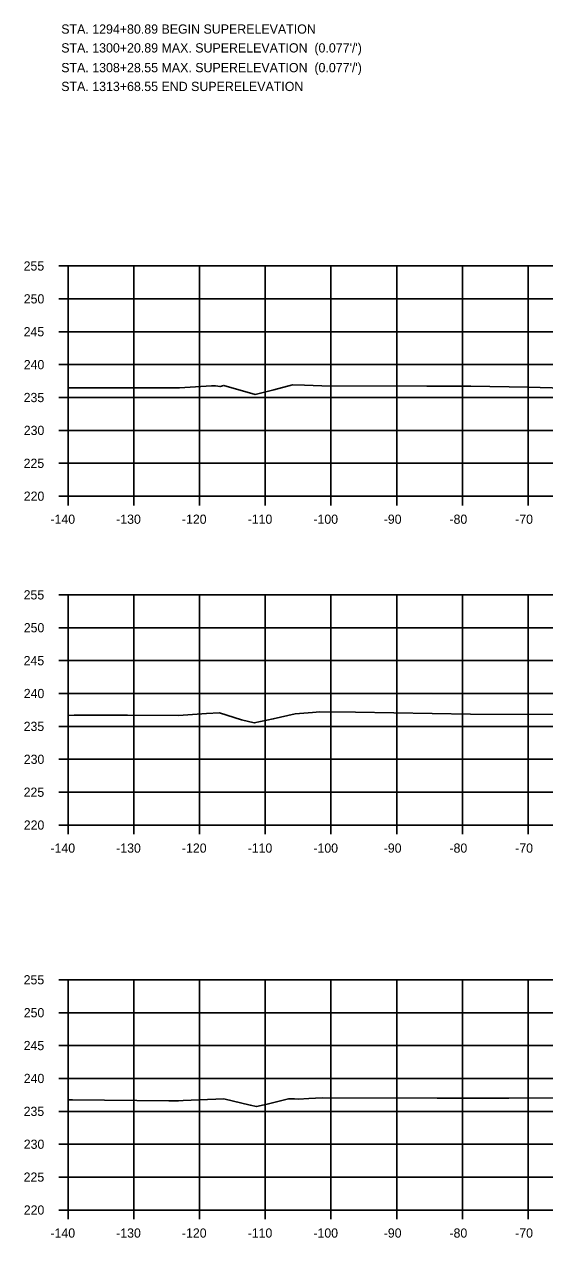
# Model space of a CAD drawing. Extents: x 1342547 to 1344156, y -1532351 to -1517216.
# Drawn here: x 1342556.2 to 1342635.4, y -1517828.4 to -1517643.9 of the extents above; entities that cross this region are included whole.
import ezdxf

# ---------------------------------------------------------------- set-up
doc = ezdxf.new("R2010")
doc.units = 0
for name, color, linetype in [('R_Axis', 7, 'Continuous'), ('R_Axis Annot', 7, 'Continuous'), ('R_Border Notes', 7, 'Continuous'), ('R_Exist Surface', 7, 'Continuous'), ('R_Grid', 7, 'Continuous')]:
    doc.layers.add(name, color=color, linetype=linetype)

msp = doc.modelspace()

# ---------------------------------------------------------------- linework, layer by layer
at = {"layer": 'R_Axis'}
for p, q in [((1342561.47, -1517680.65), (1342562.87, -1517680.65)), ((1342562.87, -1517715.65), (1342562.87, -1517680.65)), ((1342561.47, -1517685.65), (1342562.87, -1517685.65)), ((1342561.47, -1517690.65), (1342562.87, -1517690.65)), ((1342561.47, -1517695.65), (1342562.87, -1517695.65)), ((1342561.47, -1517700.65), (1342562.87, -1517700.65)), ((1342561.47, -1517705.65), (1342562.87, -1517705.65)), ((1342561.47, -1517710.65), (1342562.87, -1517710.65)), ((1342561.47, -1517715.65), (1342562.87, -1517715.65)), ((1342562.87, -1517715.65), (1342842.87, -1517715.65)), ((1342562.87, -1517717.05), (1342562.87, -1517715.65)), ((1342572.87, -1517717.05), (1342572.87, -1517715.65)), ((1342582.87, -1517717.05), (1342582.87, -1517715.65)), ((1342592.87, -1517717.05), (1342592.87, -1517715.65)), ((1342602.87, -1517717.05), (1342602.87, -1517715.65)), ((1342612.87, -1517717.05), (1342612.87, -1517715.65)), ((1342622.87, -1517717.05), (1342622.87, -1517715.65)), ((1342632.87, -1517717.05), (1342632.87, -1517715.65)), ((1342561.47, -1517730.65), (1342562.87, -1517730.65)), ((1342562.87, -1517765.65), (1342562.87, -1517730.65)), ((1342561.47, -1517735.65), (1342562.87, -1517735.65)), ((1342561.47, -1517740.65), (1342562.87, -1517740.65)), ((1342561.47, -1517745.65), (1342562.87, -1517745.65)), ((1342561.47, -1517750.65), (1342562.87, -1517750.65)), ((1342561.47, -1517755.65), (1342562.87, -1517755.65)), ((1342561.47, -1517760.65), (1342562.87, -1517760.65)), ((1342561.47, -1517765.65), (1342562.87, -1517765.65)), ((1342562.87, -1517765.65), (1342842.87, -1517765.65)), ((1342562.87, -1517767.05), (1342562.87, -1517765.65)), ((1342572.87, -1517767.05), (1342572.87, -1517765.65)), ((1342582.87, -1517767.05), (1342582.87, -1517765.65)), ((1342592.87, -1517767.05), (1342592.87, -1517765.65)), ((1342602.87, -1517767.05), (1342602.87, -1517765.65)), ((1342612.87, -1517767.05), (1342612.87, -1517765.65)), ((1342622.87, -1517767.05), (1342622.87, -1517765.65)), ((1342632.87, -1517767.05), (1342632.87, -1517765.65)), ((1342561.47, -1517789.17), (1342562.87, -1517789.17)), ((1342562.87, -1517824.17), (1342562.87, -1517789.17)), ((1342561.47, -1517794.17), (1342562.87, -1517794.17)), ((1342561.47, -1517799.17), (1342562.87, -1517799.17)), ((1342561.47, -1517804.17), (1342562.87, -1517804.17)), ((1342561.47, -1517809.17), (1342562.87, -1517809.17)), ((1342561.47, -1517814.17), (1342562.87, -1517814.17)), ((1342561.47, -1517819.17), (1342562.87, -1517819.17)), ((1342561.47, -1517824.17), (1342562.87, -1517824.17)), ((1342562.87, -1517824.17), (1342842.87, -1517824.17)), ((1342562.87, -1517825.57), (1342562.87, -1517824.17)), ((1342572.87, -1517825.57), (1342572.87, -1517824.17)), ((1342582.87, -1517825.57), (1342582.87, -1517824.17)), ((1342592.87, -1517825.57), (1342592.87, -1517824.17)), ((1342602.87, -1517825.57), (1342602.87, -1517824.17)), ((1342612.87, -1517825.57), (1342612.87, -1517824.17)), ((1342622.87, -1517825.57), (1342622.87, -1517824.17)), ((1342632.87, -1517825.57), (1342632.87, -1517824.17))]:
    msp.add_line(p, q, dxfattribs=at)
at = {"layer": 'R_Exist Surface'}
for points in [[(1342562.87, -1517699.19), (1342563.82, -1517699.18), (1342571.12, -1517699.16), (1342579.82, -1517699.2), (1342584.7, -1517698.89), (1342585.29, -1517698.85), (1342586.01, -1517698.99), (1342586.58, -1517698.81), (1342591.34, -1517700.17), (1342594.18, -1517699.46), (1342597.02, -1517698.71), (1342598.86, -1517698.75), (1342601.47, -1517698.89), (1342617.46, -1517698.9), (1342624.14, -1517698.95), (1342632.87, -1517699.07), (1342645.61, -1517699.41)], [(1342562.87, -1517748.97), (1342563.8, -1517748.95), (1342571.91, -1517748.96), (1342579.69, -1517748.99), (1342583.96, -1517748.69), (1342585.91, -1517748.58), (1342589.24, -1517749.63), (1342591.19, -1517750.13), (1342594.08, -1517749.51), (1342597.41, -1517748.76), (1342600.08, -1517748.54), (1342601.2, -1517748.46), (1342606.62, -1517748.48), (1342624.08, -1517748.77), (1342640.07, -1517748.84)], [(1342562.87, -1517807.41), (1342563.57, -1517807.41), (1342578.2, -1517807.56), (1342579.67, -1517807.56), (1342580.41, -1517807.52), (1342586.58, -1517807.29), (1342590.6, -1517808.22), (1342591.52, -1517808.45), (1342593.15, -1517808.07), (1342596.39, -1517807.27), (1342597.3, -1517807.29), (1342597.94, -1517807.3), (1342599.5, -1517807.23), (1342601.53, -1517807.11), (1342619.03, -1517807.17), (1342623.92, -1517807.17), (1342629.95, -1517807.17), (1342648.58, -1517807.13)]]:
    msp.add_lwpolyline(points, dxfattribs=at)
at = {"layer": 'R_Grid'}
for p, q in [((1342562.87, -1517680.65), (1342842.87, -1517680.65)), ((1342562.87, -1517715.65), (1342562.87, -1517680.65)), ((1342572.87, -1517715.65), (1342572.87, -1517680.65)), ((1342582.87, -1517715.65), (1342582.87, -1517680.65)), ((1342592.87, -1517715.65), (1342592.87, -1517680.65)), ((1342602.87, -1517715.65), (1342602.87, -1517680.65)), ((1342612.87, -1517715.65), (1342612.87, -1517680.65)), ((1342622.87, -1517715.65), (1342622.87, -1517680.65)), ((1342632.87, -1517715.65), (1342632.87, -1517680.65)), ((1342562.87, -1517685.65), (1342842.87, -1517685.65)), ((1342562.87, -1517690.65), (1342842.87, -1517690.65)), ((1342562.87, -1517695.65), (1342842.87, -1517695.65)), ((1342562.87, -1517700.65), (1342842.87, -1517700.65)), ((1342562.87, -1517705.65), (1342842.87, -1517705.65)), ((1342562.87, -1517710.65), (1342842.87, -1517710.65)), ((1342562.87, -1517715.65), (1342842.87, -1517715.65)), ((1342562.87, -1517730.65), (1342842.87, -1517730.65)), ((1342562.87, -1517765.65), (1342562.87, -1517730.65)), ((1342572.87, -1517765.65), (1342572.87, -1517730.65)), ((1342582.87, -1517765.65), (1342582.87, -1517730.65)), ((1342592.87, -1517765.65), (1342592.87, -1517730.65)), ((1342602.87, -1517765.65), (1342602.87, -1517730.65)), ((1342612.87, -1517765.65), (1342612.87, -1517730.65)), ((1342622.87, -1517765.65), (1342622.87, -1517730.65)), ((1342632.87, -1517765.65), (1342632.87, -1517730.65)), ((1342562.87, -1517735.65), (1342842.87, -1517735.65)), ((1342562.87, -1517740.65), (1342842.87, -1517740.65)), ((1342562.87, -1517745.65), (1342842.87, -1517745.65)), ((1342562.87, -1517750.65), (1342842.87, -1517750.65)), ((1342562.87, -1517755.65), (1342842.87, -1517755.65)), ((1342562.87, -1517760.65), (1342842.87, -1517760.65)), ((1342562.87, -1517765.65), (1342842.87, -1517765.65)), ((1342562.87, -1517789.17), (1342842.87, -1517789.17)), ((1342562.87, -1517824.17), (1342562.87, -1517789.17)), ((1342572.87, -1517824.17), (1342572.87, -1517789.17)), ((1342582.87, -1517824.17), (1342582.87, -1517789.17)), ((1342592.87, -1517824.17), (1342592.87, -1517789.17)), ((1342602.87, -1517824.17), (1342602.87, -1517789.17)), ((1342612.87, -1517824.17), (1342612.87, -1517789.17)), ((1342622.87, -1517824.17), (1342622.87, -1517789.17)), ((1342632.87, -1517824.17), (1342632.87, -1517789.17)), ((1342562.87, -1517794.17), (1342842.87, -1517794.17)), ((1342562.87, -1517799.17), (1342842.87, -1517799.17)), ((1342562.87, -1517804.17), (1342842.87, -1517804.17)), ((1342562.87, -1517809.17), (1342842.87, -1517809.17)), ((1342562.87, -1517814.17), (1342842.87, -1517814.17)), ((1342562.87, -1517819.17), (1342842.87, -1517819.17)), ((1342562.87, -1517824.17), (1342842.87, -1517824.17))]:
    msp.add_line(p, q, dxfattribs=at)

# ---------------------------------------------------------------- texts
at = {"layer": 'R_Axis Annot'}
for s, p in [('255', (1342556.12, -1517681.35)), ('250', (1342556.14, -1517686.35)), ('245', (1342556.12, -1517691.35)), ('240', (1342556.14, -1517696.35)), ('235', (1342556.12, -1517701.35)), ('230', (1342556.14, -1517706.35)), ('225', (1342556.12, -1517711.35)), ('220', (1342556.14, -1517716.35)), ('-140', (1342560.2, -1517719.85)), ('-130', (1342570.2, -1517719.85)), ('-120', (1342580.2, -1517719.85)), ('-110', (1342590.2, -1517719.85)), ('-100', (1342600.2, -1517719.85)), ('-90', (1342610.9, -1517719.85)), ('-80', (1342620.9, -1517719.85)), ('-70', (1342630.9, -1517719.85)), ('255', (1342556.12, -1517731.35)), ('250', (1342556.14, -1517736.35)), ('245', (1342556.12, -1517741.35)), ('240', (1342556.14, -1517746.35)), ('235', (1342556.12, -1517751.35)), ('230', (1342556.14, -1517756.35)), ('225', (1342556.12, -1517761.35)), ('220', (1342556.14, -1517766.35)), ('-140', (1342560.2, -1517769.85)), ('-130', (1342570.2, -1517769.85)), ('-120', (1342580.2, -1517769.85)), ('-110', (1342590.2, -1517769.85)), ('-100', (1342600.2, -1517769.85)), ('-90', (1342610.9, -1517769.85)), ('-80', (1342620.9, -1517769.85)), ('-70', (1342630.9, -1517769.85)), ('255', (1342556.12, -1517789.87)), ('250', (1342556.14, -1517794.87)), ('245', (1342556.12, -1517799.87)), ('240', (1342556.14, -1517804.87)), ('235', (1342556.12, -1517809.87)), ('230', (1342556.14, -1517814.87)), ('225', (1342556.12, -1517819.87)), ('220', (1342556.14, -1517824.87)), ('-140', (1342560.2, -1517828.37)), ('-130', (1342570.2, -1517828.37)), ('-120', (1342580.2, -1517828.37)), ('-110', (1342590.2, -1517828.37)), ('-100', (1342600.2, -1517828.37)), ('-90', (1342610.9, -1517828.37)), ('-80', (1342620.9, -1517828.37)), ('-70', (1342630.9, -1517828.37))]:
    msp.add_text(s, height=1.4, dxfattribs=at).set_placement(p)
at = {"layer": 'R_Border Notes'}
for s, p in [('STA. 1294+80.89 BEGIN SUPERELEVATION', (1342561.84, -1517645.34)), ("STA. 1300+20.89 MAX. SUPERELEVATION  (0.077'/')", (1342561.84, -1517648.2)), ("STA. 1308+28.55 MAX. SUPERELEVATION  (0.077'/')", (1342561.84, -1517651.2)), ('STA. 1313+68.55 END SUPERELEVATION', (1342561.84, -1517654.06))]:
    msp.add_text(s, height=1.41, dxfattribs=at).set_placement(p)

doc.saveas('drawing.dxf')
